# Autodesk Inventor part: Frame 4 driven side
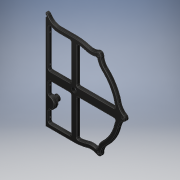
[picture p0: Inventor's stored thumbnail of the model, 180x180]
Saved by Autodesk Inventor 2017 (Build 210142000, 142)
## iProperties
Created: 2016-06
Part Number: Frame 4 driven side
Material: Generic
Document SubType Name: Modeling
Designer: Stan
Density: 1 g/cm^3
Appearance: Glossy - Black
Author: Stan
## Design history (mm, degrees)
sketch "Sketch1"
  geometry: L1 (-33.07, 98.425)-(0, 98.425); L2 (-33.07, 88.9)-(-9.525, 88.9); L3 (-60.566, -98.425)-(0, -98.425); L4 (-51.041, -9.525)-(-9.525, -9.525); L5 (9.525, -9.525)-(85.613, -9.525); L6 (-51.041, 9.525)-(-9.525, 9.525); L7 (9.525, 9.525)-(85.613, 9.525); L8 (-51.041, -88.9)-(-9.525, -88.9); L9 (-6.35, -12.7)-(-6.35, -85.725); L10 (6.35, -12.7)-(6.35, -85.194); L11 (-6.35, 12.7)-(-6.35, 85.725); L12 (6.35, 12.7)-(6.35, 85.194); L13 (-60.566, 114.3)-(-60.566, 110.49); L14 (-60.566, 105.41)-(-60.566, -98.425); L15 (-54.216, 90.23)-(-54.216, 12.7); L16 (-54.216, -12.7)-(-54.216, -34.676); L17 (-54.216, -65.908)-(-54.216, -85.725); C1 r 5.159 at (0, 0); C2 r 2.54 at (104.775, 0); C3 r 2.54 at (52.388, -90.738); C4 r 2.54 at (52.388, 90.738); C5 r 3.175 at (-53.899, -50.292); A1 r 3.175 centre (-9.525, 85.725) between (-6.35, 85.725) and (-9.525, 88.9); A2 r 3.175 centre (-51.041, -12.7) between (-51.041, -9.525) and (-54.216, -12.7); A3 r 3.175 centre (-9.525, -12.7) between (-6.35, -12.7) and (-9.525, -9.525); A4 r 3.175 centre (-9.525, 12.7) between (-9.525, 9.525) and (-6.35, 12.7); A5 r 3.175 centre (9.525, 12.7) between (6.35, 12.7) and (9.525, 9.525); A6 r 98.425 centre (0, 0) between (0, -98.425) and (29.099, -94.025); A7 r 98.425 centre (0, 0) between (66.878, -72.213) and (95.978, -21.812); A8 r 98.425 centre (0, 0) between (95.978, 21.812) and (66.878, 72.213); A9 r 98.425 centre (0, 0) between (29.099, 94.025) and (0, 98.425); A10 r 88.9 centre (0, 0) between (9.878, -88.35) and (26.283, -84.926); A11 r 88.9 centre (0, 0) between (60.406, -65.225) and (86.69, -19.701); A12 r 3.175 centre (9.525, -85.194) between (6.35, -85.194) and (9.878, -88.35); A13 r 88.9 centre (0, 0) between (86.69, 19.701) and (60.406, 65.225); A14 r 88.9 centre (0, 0) between (26.283, 84.926) and (9.878, 88.35); A15 r 3.175 centre (9.525, 85.194) between (9.878, 88.35) and (6.35, 85.194); A16 r 6.35 centre (104.775, 0) between (107.969, -5.488) and (107.969, 5.488); A17 r 25.4 centre (120.746, 27.441) between (95.978, 21.812) and (107.969, 5.488); A18 r 34.925 centre (120.746, 27.441) between (86.69, 19.701) and (88.541, 13.928); A19 r 3.175 centre (85.613, 12.7) between (85.613, 9.525) and (88.541, 13.928); A20 r 25.4 centre (120.746, -27.441) between (107.969, -5.488) and (95.978, -21.812); A21 r 34.925 centre (120.746, -27.441) between (88.541, -13.928) and (86.69, -19.701); A22 r 3.175 centre (85.613, -12.7) between (88.541, -13.928) and (85.613, -9.525); A23 r 6.35 centre (52.388, -90.738) between (49.232, -96.248) and (58.737, -90.76); A24 r 25.4 centre (84.137, -90.849) between (66.878, -72.213) and (58.737, -90.76); A25 r 34.925 centre (84.137, -90.849) between (60.406, -65.225) and (50.239, -82.443); A26 r 25.4 centre (36.609, -118.29) between (49.232, -96.248) and (29.099, -94.025); A27 r 34.925 centre (36.609, -118.29) between (46.278, -84.73) and (26.283, -84.926); A28 r 3.175 centre (47.157, -81.679) between (46.278, -84.73) and (50.239, -82.443); A29 r 6.35 centre (52.388, 90.738) between (58.737, 90.76) and (49.232, 96.248); A30 r 25.4 centre (36.609, 118.29) between (29.099, 94.025) and (49.232, 96.248); A31 r 34.925 centre (36.609, 118.29) between (26.283, 84.926) and (46.278, 84.73); A32 r 25.4 centre (84.137, 90.849) between (58.737, 90.76) and (66.878, 72.213); A33 r 34.925 centre (84.137, 90.849) between (50.239, 82.443) and (60.406, 65.225); A34 r 3.175 centre (47.157, 81.679) between (50.239, 82.443) and (46.278, 84.73); A35 r 6.35 centre (-60.566, 107.95) between (-55.067, 111.125) and (-60.566, 114.3); A36 r 25.4 centre (-33.07, 123.825) between (-55.067, 111.125) and (-33.07, 98.425); A37 r 34.925 centre (-33.07, 123.825) between (-49.544, 93.029) and (-33.07, 88.9); A38 r 3.175 centre (-51.041, 90.23) between (-49.544, 93.029) and (-54.216, 90.23); A39 r 2.54 centre (-60.566, 107.95) between (-60.566, 105.41) and (-60.566, 110.49); A40 r 3.175 centre (-9.525, -85.725) between (-9.525, -88.9) and (-6.35, -85.725); A41 r 3.175 centre (9.525, -12.7) between (9.525, -9.525) and (6.35, -12.7); A42 r 3.175 centre (-51.041, 12.7) between (-54.216, 12.7) and (-51.041, 9.525); A43 r 3.175 centre (-51.041, -85.725) between (-54.216, -85.725) and (-51.041, -88.9); A44 r 12.7 centre (-53.899, -50.292) between (-51.613, -62.785) and (-51.613, -37.799); A45 r 3.175 centre (-51.041, -34.676) between (-54.216, -34.676) and (-51.613, -37.799); A46 r 3.175 centre (-51.041, -65.908) between (-51.613, -62.785) and (-54.216, -65.908); 4 further points
  constraints: 94 point on circle, 51 centre point, 34 end point, 4 tangent, 3 point on line, 1 equal radius
  dimensions: "d0" = 10.31875 diameter of C1; "d22" = 60.5663 distance from line of point (0, 0) L14; "d23" = 6.6675 distance from line of L14 C5.centre; "d24" = 6.35 distance between parallel lines of L14 L16; "d25" = 6.35 distance between parallel lines of L14 L17; "d26" = 50.292 vertical distance of C5.centre point (0, 0); "d27" = 3.175 radius of A45 (derived); "d28" = 12.7 radius of A44
extrude "Extrusion1" new body sketch "Sketch1" distance "d1" = 6.35; taper "d2" = 0 deg
fillet "Fillet1" dims "d3" = 1.5875
sketch "Sketch2"
  geometry: L1 (6.35, 203.835)-(6.35, 1.587) reference; C1 r 1.587 at (3.175, 79.375); C2 r 1.587 at (3.175, 117.475); C3 r 1.587 at (3.175, 177.8); C4 r 1.587 at (3.175, 19.05); 3 further points
  constraints: 4 centre point
  dimensions: "d5" = 9.525 vertical distance of C1.centre point (4.763, 88.9); "d6" = 9.525 vertical distance of C2.centre point (4.763, 107.95); "d7" = 60.325 distance of C3.centre C2.centre; "d8" = 60.325 distance of C4.centre C1.centre; "d9" = 3.175 distance from line of L1 C1.centre; "d10" = 3.175 distance from line of L1 C2.centre; "d11" = 3.175 distance from line of L1 C3.centre; "d12" = 3.175 distance from line of L1 C4.centre; "d13" = 3.175 diameter of C4; "d14" = 3.175 diameter of C1; "d15" = 3.175 diameter of C2; "d16" = 3.175 diameter of C3
extrude "Extrusion2" cut sketch "Sketch2" distance "d17" = 6.35; taper "d18" = 0 deg
sketch "Sketch3"
  geometry: L1 (60.566, -98.425)-(60.566, 105.41) reference; L2 (60.566, -59.182)-(60.566, -41.402); C1 r 3.175 at (53.899, -50.292) reference; C2 r 3.175 at (53.899, -50.292); A1 r 11.112 centre (53.899, -50.292) between (60.566, -41.402) and (60.566, -59.182); 1 further point
  constraints: 2 centre point, 2 coincident, 2 end point, 2 point on circle, 2 point on line
extrude "Extrusion3" join sketch "Sketch3" distance "d29" = 3.175; taper "d30" = 0 deg
sketch "Sketch4"
  geometry: C1 r 3.175 at (53.899, -50.292) reference; C2 r 3.175 at (53.899, -50.292); C3 r 6.35 at (53.899, -50.292); 1 further point
  constraints: 2 centre point, 2 coincident
  dimensions: "d31" = 12.7 diameter of C3
extrude "Extrusion4" join sketch "Sketch4" distance "d32" = 9.525; taper "d33" = 0 deg
fillet "Fillet2" dims "d34" = 3.175
sketch "Sketch5"
  geometry: C1 r 3.175 at (-53.899, -50.292) reference; C2 r 3.175 at (-53.899, -50.292); 1 further point
  constraints: 1 centre point, 1 coincident
extrude "Extrusion5" join sketch "Sketch5" distance "d35" = 1.5875; taper "d36" = 0 deg
body "Solid1"
